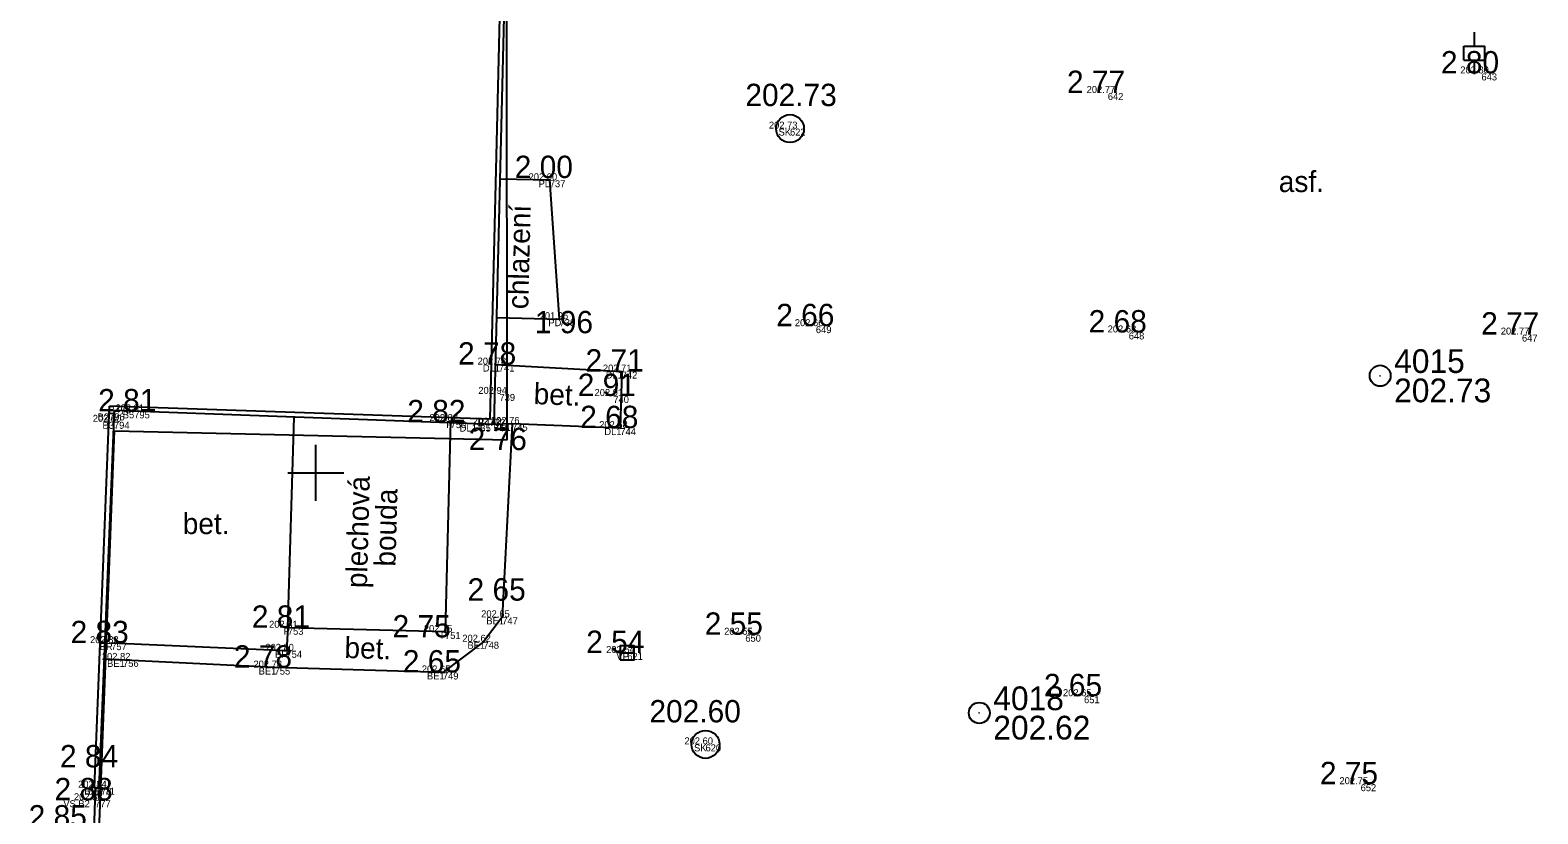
# Model space of a CAD drawing. Extents: x -599717 to -599336, y -1161826 to -1161587.
# Drawn here: x -599564.09 to -599542.5, y -1161704.88 to -1161693.66 of the extents above; entities that cross this region are included whole.
import ezdxf

# ---------------------------------------------------------------- set-up
doc = ezdxf.new("R2010")
doc.units = 0
for name, color, linetype in [('BODY', 7, 'Continuous'), ('BODY_CISLA', 7, 'Continuous'), ('BODY_KODY', 7, 'Continuous'), ('BODY_POLYGONY', 7, 'Continuous'), ('BODY_VYSKY_CELE', 7, 'Continuous'), ('G_BUDOVY', 7, 'Continuous'), ('G_POLOHOPIS', 7, 'Continuous'), ('G_TEXTY', 7, 'Continuous'), ('G_VSTUPY', 7, 'Continuous'), ('G_ZNACKY', 7, 'Continuous'), ('H_KOTY_VYSKOVE', 7, 'Continuous'), ('KN_Vnitřní kresba', 7, 'Continuous'), ('KN_Značky kultur', 7, 'Continuous'), ('X_SOUR_KRIZKY_SEVER', 7, 'Continuous')]:
    doc.layers.add(name, color=color, linetype=linetype)

msp = doc.modelspace()

# ---------------------------------------------------------------- linework, layer by layer
at = {"layer": 'BODY'}
for p, q in [((-599543.31, -1161694.28), (-599543.31, -1161694.28)), ((-599548.66, -1161694.56), (-599548.66, -1161694.56)), ((-599553.21, -1161695.07), (-599553.21, -1161695.07)), ((-599556.65, -1161695.81), (-599556.65, -1161695.81)), ((-599556.51, -1161697.8), (-599556.51, -1161697.8)), ((-599552.84, -1161697.9), (-599552.84, -1161697.9)), ((-599548.36, -1161697.99), (-599548.36, -1161697.99)), ((-599542.73, -1161698.02), (-599542.73, -1161698.02)), ((-599557.38, -1161698.45), (-599557.38, -1161698.45)), ((-599555.62, -1161698.55), (-599555.62, -1161698.55)), ((-599557.37, -1161698.87), (-599557.37, -1161698.87)), ((-599555.74, -1161698.9), (-599555.74, -1161698.9)), ((-599562.96, -1161699.15), (-599562.96, -1161699.15)), ((-599562.8, -1161699.05), (-599562.8, -1161699.05)), ((-599562.6, -1161699.12), (-599562.6, -1161699.12)), ((-599562.89, -1161699.27), (-599562.89, -1161699.27)), ((-599558.07, -1161699.26), (-599558.07, -1161699.26)), ((-599557.51, -1161699.23), (-599557.51, -1161699.23)), ((-599557.45, -1161699.31), (-599557.45, -1161699.31)), ((-599557.19, -1161699.3), (-599557.19, -1161699.3)), ((-599555.64, -1161699.36), (-599555.64, -1161699.36)), ((-599560.4, -1161702.22), (-599560.4, -1161702.22)), ((-599557.33, -1161702.07), (-599557.33, -1161702.07)), ((-599562.93, -1161702.44), (-599562.93, -1161702.44)), ((-599558.15, -1161702.28), (-599558.15, -1161702.28)), ((-599557.6, -1161702.42), (-599557.6, -1161702.42)), ((-599553.85, -1161702.32), (-599553.85, -1161702.32)), ((-599560.42, -1161702.55), (-599560.42, -1161702.55)), ((-599555.54, -1161702.58), (-599555.54, -1161702.58)), ((-599562.76, -1161702.68), (-599562.76, -1161702.68)), ((-599560.59, -1161702.79), (-599560.59, -1161702.79)), ((-599558.18, -1161702.86), (-599558.18, -1161702.86)), ((-599549, -1161703.2), (-599549, -1161703.2)), ((-599554.42, -1161703.89), (-599554.42, -1161703.89)), ((-599563.15, -1161704.51), (-599563.15, -1161704.51)), ((-599563.1, -1161704.51), (-599563.1, -1161704.51)), ((-599545.04, -1161704.46), (-599545.04, -1161704.46)), ((-599563.16, -1161704.69), (-599563.16, -1161704.69))]:
    msp.add_line(p, q, dxfattribs=at)
at = {"layer": 'BODY_POLYGONY'}
for centre, radius in [((-599544.76, -1161698.61), 0.15), ((-599544.76, -1161698.61), 0.0002), ((-599550.5, -1161703.44), 0.15), ((-599550.5, -1161703.44), 0.0002)]:
    msp.add_circle(centre, radius, dxfattribs=at)
at = {"layer": 'G_BUDOVY'}
msp.add_line((-599563.15, -1161704.51), (-599563.17, -1161704.509), dxfattribs=at)
for points in [[(-599557.23, -1161689.29), (-599557.35, -1161692.68), (-599557.51, -1161699.23), (-599562.956, -1161699.045)], [(-599557.35, -1161692.688), (-599557.29, -1161692.69), (-599557.45, -1161699.31), (-599562.884, -1161699.11)], [(-599563.17, -1161704.509), (-599562.956, -1161699.045)], [(-599563.15, -1161704.51), (-599563.1, -1161704.51), (-599562.884, -1161699.11)], [(-599563.16, -1161704.69), (-599563.15, -1161704.51)]]:
    msp.add_lwpolyline(points, dxfattribs=at)
at = {"layer": 'G_POLOHOPIS'}
msp.add_line((-599560.4, -1161702.22), (-599560.311, -1161699.204), dxfattribs=at)
for points in [[(-599557.413, -1161697.778), (-599556.51, -1161697.8), (-599556.65, -1161695.81), (-599557.365, -1161695.793)], [(-599557.429, -1161698.447), (-599555.62, -1161698.55), (-599555.64, -1161699.36), (-599557.19, -1161699.3), (-599557.45, -1161699.31)], [(-599557.19, -1161699.3), (-599557.33, -1161702.07), (-599557.6, -1161702.42), (-599558.18, -1161702.86), (-599560.59, -1161702.79), (-599563.026, -1161702.667)], [(-599558.07, -1161699.26), (-599558.15, -1161702.28), (-599560.4, -1161702.22), (-599560.42, -1161702.55)]]:
    msp.add_lwpolyline(points, dxfattribs=at)
at = {"layer": 'G_VSTUPY'}
for points in [[(-599560.42, -1161702.55), (-599562.93, -1161702.44)], [(-599563.2, -1161706.01), (-599563.16, -1161704.69)]]:
    msp.add_lwpolyline(points, dxfattribs=at)
at = {"layer": 'G_ZNACKY'}
msp.add_line((-599555.64, -1161702.58), (-599555.44, -1161702.58), dxfattribs=at)
msp.add_lwpolyline([(-599555.64, -1161702.68), (-599555.44, -1161702.68), (-599555.44, -1161702.48), (-599555.64, -1161702.48)], close=True, dxfattribs=at)
for centre in [(-599553.21, -1161695.07), (-599554.42, -1161703.89)]:
    msp.add_circle(centre, 0.2, dxfattribs=at)
at = {"layer": 'KN_Vnitřní kresba'}
for p, q in [((-599557.26, -1161699.53), (-599557.27, -1161689.42)), ((-599563.47, -1161714.76), (-599562.88, -1161699.4)), ((-599562.88, -1161699.4), (-599557.26, -1161699.53))]:
    msp.add_line(p, q, dxfattribs=at)
at = {"layer": 'KN_Značky kultur'}
for p, q in [((-599543.41, -1161693.89), (-599543.41, -1161693.69)), ((-599543.56, -1161693.89), (-599543.26, -1161693.89)), ((-599543.56, -1161694.09), (-599543.56, -1161693.89)), ((-599543.26, -1161694.09), (-599543.26, -1161693.89)), ((-599543.56, -1161694.09), (-599543.26, -1161694.09)), ((-599543.41, -1161694.29), (-599543.41, -1161694.09))]:
    msp.add_line(p, q, dxfattribs=at)
at = {"layer": 'X_SOUR_KRIZKY_SEVER'}
for p, q in [((-599560, -1161700.4), (-599560, -1161699.6)), ((-599560.4, -1161700), (-599559.6, -1161700))]:
    msp.add_line(p, q, dxfattribs=at)

# ---------------------------------------------------------------- texts
at = {"layer": 'BODY_CISLA'}
for s, p in [('643', (-599543.31, -1161694.38)), ('642', (-599548.66, -1161694.66)), ('622', (-599553.21, -1161695.17)), ('737', (-599556.65, -1161695.91)), ('738', (-599556.51, -1161697.9)), ('649', (-599552.84, -1161698)), ('648', (-599548.36, -1161698.09)), ('647', (-599542.73, -1161698.12)), ('741', (-599557.38, -1161698.55)), ('742', (-599555.62, -1161698.65)), ('739', (-599557.37, -1161698.97)), ('740', (-599555.74, -1161699)), ('796', (-599562.96, -1161699.25)), ('797', (-599562.8, -1161699.15)), ('795', (-599562.6, -1161699.22)), ('794', (-599562.89, -1161699.37)), ('750', (-599558.07, -1161699.36)), ('732', (-599557.51, -1161699.33)), ('746', (-599557.45, -1161699.41)), ('745', (-599557.19, -1161699.4)), ('744', (-599555.64, -1161699.46)), ('753', (-599560.4, -1161702.32)), ('747', (-599557.33, -1161702.17)), ('757', (-599562.93, -1161702.54)), ('751', (-599558.15, -1161702.38)), ('748', (-599557.6, -1161702.52)), ('650', (-599553.85, -1161702.42)), ('754', (-599560.42, -1161702.65)), ('621', (-599555.54, -1161702.68)), ('756', (-599562.76, -1161702.78)), ('755', (-599560.59, -1161702.89)), ('749', (-599558.18, -1161702.96)), ('651', (-599549, -1161703.3)), ('620', (-599554.42, -1161703.99)), ('778', (-599563.15, -1161704.61)), ('771', (-599563.1, -1161704.61)), ('652', (-599545.04, -1161704.56)), ('777', (-599563.16, -1161704.79))]:
    msp.add_text(s, height=0.1, dxfattribs=at).set_placement(p)
at = {"layer": 'BODY_KODY'}
for s, p in [('SK', (-599553.374, -1161695.17)), ('PD', (-599556.81, -1161695.91)), ('PD', (-599556.67, -1161697.9)), ('DL1', (-599557.608, -1161698.55)), ('DL1', (-599555.848, -1161698.65)), ('B2', (-599563.124, -1161699.25)), ('B4', (-599562.964, -1161699.15)), ('B5', (-599562.764, -1161699.22)), ('B3', (-599563.054, -1161699.37)), ('P', (-599558.131, -1161699.36)), ('DL1 B5', (-599557.94, -1161699.41)), ('DL1 BE1', (-599557.744, -1161699.4)), ('B4', (-599557.674, -1161699.33)), ('DL1', (-599555.868, -1161699.46)), ('P', (-599560.461, -1161702.32)), ('BE1', (-599557.558, -1161702.17)), ('BR', (-599563.094, -1161702.54)), ('P', (-599558.211, -1161702.38)), ('BE1', (-599557.828, -1161702.52)), ('BR', (-599560.584, -1161702.65)), ('VP', (-599555.696, -1161702.68)), ('BE1', (-599562.988, -1161702.78)), ('BE1', (-599560.818, -1161702.89)), ('BE1', (-599558.408, -1161702.96)), ('SK', (-599554.584, -1161703.99)), ('B2', (-599563.314, -1161704.61)), ('B3', (-599563.264, -1161704.61)), ('VS B2', (-599563.615, -1161704.79))]:
    msp.add_text(s, height=0.1, dxfattribs=at).set_placement(p)
at = {"layer": 'BODY_POLYGONY'}
for s, p in [('4015', (-599544.56, -1161698.57)), ('202.73', (-599544.56, -1161698.99)), ('4018', (-599550.3, -1161703.4)), ('202.62', (-599550.3, -1161703.82))]:
    msp.add_text(s, height=0.34, dxfattribs=at).set_placement(p)
at = {"layer": 'BODY_VYSKY_CELE'}
for s, p in [('202.80 ', (-599543.613, -1161694.28)), ('202.77 ', (-599548.963, -1161694.56)), ('202.73 ', (-599553.512, -1161695.07)), ('202.00 ', (-599556.953, -1161695.81)), ('201.96 ', (-599556.795, -1161697.8)), ('202.66 ', (-599553.141, -1161697.9)), ('202.68 ', (-599548.662, -1161697.99)), ('202.77 ', (-599543.033, -1161698.02)), ('202.78 ', (-599557.683, -1161698.45)), ('202.71 ', (-599555.889, -1161698.55)), ('202.94 ', (-599557.673, -1161698.87)), ('202.91 ', (-599556.009, -1161698.9)), ('202.80 ', (-599563.193, -1161699.27)), ('202.81 ', (-599562.869, -1161699.12)), ('202.82 ', (-599558.373, -1161699.26)), ('202.82 ', (-599557.753, -1161699.31)), ('202.76 ', (-599557.492, -1161699.3)), ('202.68 ', (-599555.942, -1161699.36)), ('202.65 ', (-599557.632, -1161702.07)), ('202.81 ', (-599560.669, -1161702.22)), ('202.75 ', (-599558.453, -1161702.28)), ('202.55 ', (-599554.153, -1161702.32)), ('202.83 ', (-599563.232, -1161702.44)), ('202.80 ', (-599560.723, -1161702.55)), ('202.62 ', (-599557.902, -1161702.42)), ('202.82 ', (-599563.063, -1161702.68)), ('202.54 ', (-599555.843, -1161702.58)), ('202.78 ', (-599560.893, -1161702.79)), ('202.65 ', (-599558.482, -1161702.86)), ('202.65 ', (-599549.302, -1161703.2)), ('202.60 ', (-599554.722, -1161703.89)), ('202.75 ', (-599545.343, -1161704.46)), ('202.88 ', (-599563.463, -1161704.69)), ('202.84 ', (-599563.403, -1161704.51))]:
    msp.add_text(s, height=0.1, dxfattribs=at).set_placement(p)
at = {"layer": 'G_TEXTY'}
for s, p in [('asf.', (-599546.212, -1161695.979)), ('bet.', (-599561.905, -1161700.878))]:
    msp.add_text(s, height=0.3, dxfattribs=at).set_placement(p)
for s, rotation, p in [('chlazení', 88.6155, (-599556.959, -1161697.659)), ('bet.', 357.7832, (-599556.885, -1161699.015)), ('plechová ', 88.4826, (-599559.269, -1161701.655)), ('bouda', 88.4826, (-599558.86, -1161701.346)), ('bet.', 358.3363, (-599559.593, -1161702.652))]:
    msp.add_text(s, height=0.3, rotation=rotation, dxfattribs=at).set_placement(p)
at = {"layer": 'H_KOTY_VYSKOVE'}
for s, p in [(' 2 80', (-599544.009, -1161694.28)), (' 2 77', (-599549.363, -1161694.56)), ('202.73 ', (-599553.849, -1161694.748)), (' 2 00', (-599557.27, -1161695.778)), (' 1 96', (-599556.982, -1161698.001)), (' 2 66', (-599553.526, -1161697.9)), (' 2 68', (-599549.053, -1161697.99)), (' 2 77', (-599543.433, -1161698.02)), (' 2 78', (-599558.082, -1161698.45)), (' 2 71', (-599556.257, -1161698.55)), (' 2 91', (-599556.368, -1161698.9)), (' 2 81', (-599563.235, -1161699.12)), (' 2 82', (-599558.809, -1161699.276)), (' 2 68', (-599556.333, -1161699.36)), (' 2 76', (-599557.93, -1161699.675)), (' 2 65', (-599557.946, -1161701.831)), (' 2 81', (-599561.035, -1161702.22)), (' 2 55', (-599554.55, -1161702.32)), (' 2 83', (-599563.63, -1161702.44)), (' 2 75', (-599559.02, -1161702.358)), (' 2 54', (-599556.247, -1161702.58)), (' 2 78', (-599561.292, -1161702.79)), (' 2 65', (-599558.873, -1161702.86)), (' 2 65', (-599549.693, -1161703.2)), ('202.60 ', (-599555.223, -1161703.575)), (' 2 84', (-599563.782, -1161704.219)), (' 2 75', (-599545.742, -1161704.46)), (' 2 88', (-599563.86, -1161704.69)), (' 2 85', (-599564.23, -1161705.08))]:
    msp.add_text(s, height=0.32, dxfattribs=at).set_placement(p)

doc.saveas('drawing.dxf')
